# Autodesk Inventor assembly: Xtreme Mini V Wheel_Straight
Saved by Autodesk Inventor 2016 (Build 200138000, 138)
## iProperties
Created: 2016-01
Part Number: Xtreme Mini V Wheel_Straight
Document SubType Name: Assembly
Designer: John
Author: John
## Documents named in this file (6)
- D:\3D Printer Designs\John Ledden Designs\DLP Printer\V2\Xtreme Mini V Wheel_Straight.iam
- D:\3D Printer Designs\John Ledden Designs\DLP Printer\V2\Ball Bearing 5 x 10 x 4.2.ipt
- D:\3D Printer Designs\John Ledden Designs\DLP Printer\V2\Precision Shim 8 x 5 x 1.ipt
- D:\3D Printer Designs\John Ledden Designs\DLP Printer\V2\Xtreme Mini V Wheel.ipt
- D:\3D Printer Designs\John Ledden Designs\DLP Printer\V2\Aluminum Spacer 6mm.ipt
- D:\3D Printer Designs\John Ledden Designs\DLP Printer\V2\Nylon Insert Lock Nut M5.ipt
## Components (7 placed, 7 different names)
1. Ball Bearing 5 x 10 x 4.2_1007
2. Precision Shim 8 x 5 x 1_1008
3. Xtreme Mini V Wheel_1009
4. Precision Shim 8 x 5 x 1_1010
5. Aluminum Spacer 6mm_1011
6. Ball Bearing 5 x 10 x 4.2_1012
7. Nylon Insert Lock Nut M5_1013
